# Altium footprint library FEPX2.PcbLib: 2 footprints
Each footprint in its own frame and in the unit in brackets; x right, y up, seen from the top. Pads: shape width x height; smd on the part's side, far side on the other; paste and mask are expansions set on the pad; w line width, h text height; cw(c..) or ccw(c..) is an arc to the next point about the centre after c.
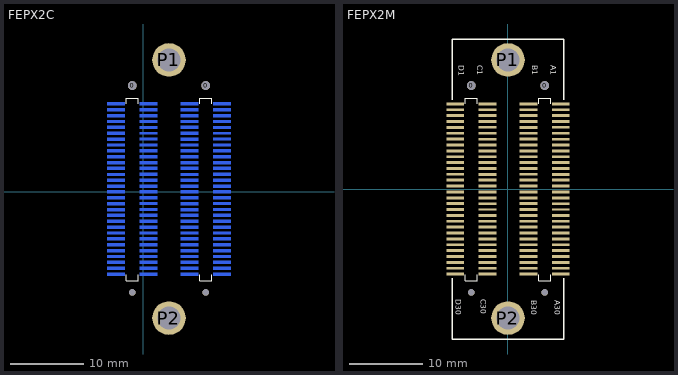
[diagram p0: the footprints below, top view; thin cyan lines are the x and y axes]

## FEPX2C [mm]
pads (126):
  round 0.889 hole 0.889: 0(-1.469,-13.691) 0(8.531,-13.691)
  round 1.2 hole 1.2: 0(-1.469,14.509) 0(8.531,14.509)
  rect 2.4x0.4 smd far side: A1(10.731,12.009) A2(10.731,11.209) A3(10.731,10.409) A4(10.731,9.609) A8(10.731,6.409) A9(10.731,5.609) A10(10.731,4.809) A11(10.731,4.009) A12(10.731,3.209) A13(10.731,2.409) A14(10.731,1.609) A15(10.731,0.809) A16(10.731,0.009) A17(10.731,-0.791) A20(10.731,-3.191) A21(10.731,-3.991) A22(10.731,-4.791) A23(10.731,-5.591) A24(10.731,-6.391) A25(10.731,-7.191) A26(10.731,-7.991) A27(10.731,-8.791) A28(10.731,-9.591) A29(10.731,-10.391) A30(10.731,-11.191) B1(6.331,12.009) B2(6.331,11.209) B3(6.331,10.409) B4(6.331,9.609) B5(6.331,8.809) B6(6.331,8.009) B7(6.331,7.209) B8(6.331,6.409) B9(6.331,5.609) B10(6.331,4.809) B11(6.331,4.009) B12(6.331,3.209) B14(6.331,1.609) B15(6.331,0.809) B16(6.331,0.009) B17(6.331,-0.791) B18(6.331,-1.591) B19(6.331,-2.391) B20(6.331,-3.191) B21(6.331,-3.991) B22(6.331,-4.791) B23(6.331,-5.591) B24(6.331,-6.391) B25(6.331,-7.191) B26(6.331,-7.991) B27(6.331,-8.791) B28(6.331,-9.591) B29(6.331,-10.391) B30(6.331,-11.191) C1(0.731,12.009) C2(0.731,11.209) C3(0.731,10.409) C4(0.731,9.609) C8(0.731,6.409) C9(0.731,5.609) C10(0.731,4.809) C11(0.731,4.009) C12(0.731,3.209) C13(0.731,2.409) C14(0.731,1.609) C15(0.731,0.809) C16(0.731,0.009) C17(0.731,-0.791) C20(0.731,-3.191) C21(0.731,-3.991) C22(0.731,-4.791) C23(0.731,-5.591) C24(0.731,-6.391) C25(0.731,-7.191) C26(0.731,-7.991) C27(0.731,-8.791) C28(0.731,-9.591) C29(0.731,-10.391) C30(0.731,-11.191) D1(-3.669,12.009) D2(-3.669,11.209) D3(-3.669,10.409) D4(-3.669,9.609) D5(-3.669,8.809) D6(-3.669,8.009) D7(-3.669,7.209) D8(-3.669,6.409) D9(-3.669,5.609) D10(-3.669,4.809) D11(-3.669,4.009) D12(-3.669,3.209) D14(-3.669,1.609) D15(-3.669,0.809) D16(-3.669,0.009) D17(-3.669,-0.791) D18(-3.669,-1.591) D19(-3.669,-2.391) D20(-3.669,-3.191) D21(-3.669,-3.991) D22(-3.669,-4.791) D23(-3.669,-5.591) D24(-3.669,-6.391) D25(-3.669,-7.191) D26(-3.669,-7.991) D27(-3.669,-8.791) D28(-3.669,-9.591) D29(-3.669,-10.391) D30(-3.669,-11.191)
  rect 2.4x0.33 smd far side: A5(10.731,8.809) A6(10.731,8.009) A7(10.731,7.209) A18(10.731,-1.591) A19(10.731,-2.391) B13(6.331,2.409) C5(0.731,8.809) C6(0.731,8.009) C7(0.731,7.209) C18(0.731,-1.591) C19(0.731,-2.391) D13(-3.669,2.409)
  round 4.57 hole 3.1: P1(3.531,18.009) P2(3.531,-17.191)
Top Overlay:
  lines w0.152: -2.269,-11.291 -2.269,-12.091 -0.669,-12.091 ; -2.269,12.009 -2.269,12.809 -0.669,12.809 -0.669,12.009 ; 7.731,12.009 7.731,12.809 9.331,12.809 9.331,12.009 ; 9.331,-11.291 9.331,-12.091 7.731,-12.091 ; -0.669,-12.091 -0.669,-11.291 -0.669,-12.091 ; 7.731,-12.091 7.731,-11.291 7.731,-12.091
Bottom Overlay:
  lines w0.203: -4.089,-11.786 -4.089,-20.041 11.151,-20.041 11.151,-11.786 ; -4.089,12.604 -4.089,20.859 11.151,20.859 11.151,12.604
  text "D1" at -3.2,17.247 h0.76
  text "C1" at -0.66,17.247 h0.76
  text "D30" at -3.581,-14.63 h0.76
  text "C30" at -0.152,-14.63 h0.76
  text "B30" at 6.706,-14.757 h0.76
  text "A30" at 9.881,-14.757 h0.76
  text "B1" at 6.833,17.247 h0.76
  text "A1" at 9.373,17.247 h0.76

## FEPX2M [mm]
pads (126):
  round 0.889 hole 0.889: 0(-5,-14.1) 0(5,-14.1)
  round 1.2 hole 1.2: 0(-5,14.1) 0(5,14.1)
  rect 2.4x0.4 smd: A1(7.2,11.6) A2(7.2,10.8) A3(7.2,10) A4(7.2,9.2) A8(7.2,6) A9(7.2,5.2) A10(7.2,4.4) A11(7.2,3.6) A12(7.2,2.8) A13(7.2,2) A14(7.2,1.2) A15(7.2,0.4) A16(7.2,-0.4) A17(7.2,-1.2) A20(7.2,-3.6) A21(7.2,-4.4) A22(7.2,-5.2) A23(7.2,-6) A24(7.2,-6.8) A25(7.2,-7.6) A26(7.2,-8.4) A27(7.2,-9.2) A28(7.2,-10) A29(7.2,-10.8) A30(7.2,-11.6) B1(2.8,11.6) B2(2.8,10.8) B3(2.8,10) B4(2.8,9.2) B5(2.8,8.4) B6(2.8,7.6) B7(2.8,6.8) B8(2.8,6) B9(2.8,5.2) B10(2.8,4.4) B11(2.8,3.6) B12(2.8,2.8) B14(2.8,1.2) B15(2.8,0.4) B16(2.8,-0.4) B17(2.8,-1.2) B18(2.8,-2) B19(2.8,-2.8) B20(2.8,-3.6) B21(2.8,-4.4) B22(2.8,-5.2) B23(2.8,-6) B24(2.8,-6.8) B25(2.8,-7.6) B26(2.8,-8.4) B27(2.8,-9.2) B28(2.8,-10) B29(2.8,-10.8) B30(2.8,-11.6) C1(-2.8,11.6) C2(-2.8,10.8) C3(-2.8,10) C4(-2.8,9.2) C8(-2.8,6) C9(-2.8,5.2) C10(-2.8,4.4) C11(-2.8,3.6) C12(-2.8,2.8) C13(-2.8,2) C14(-2.8,1.2) C15(-2.8,0.4) C16(-2.8,-0.4) C17(-2.8,-1.2) C20(-2.8,-3.6) C21(-2.8,-4.4) C22(-2.8,-5.2) C23(-2.8,-6) C24(-2.8,-6.8) C25(-2.8,-7.6) C26(-2.8,-8.4) C27(-2.8,-9.2) C28(-2.8,-10) C29(-2.8,-10.8) C30(-2.8,-11.6) D1(-7.2,11.6) D2(-7.2,10.8) D3(-7.2,10) D4(-7.2,9.2) D5(-7.2,8.4) D6(-7.2,7.6) D7(-7.2,6.8) D8(-7.2,6) D9(-7.2,5.2) D10(-7.2,4.4) D11(-7.2,3.6) D12(-7.2,2.8) D14(-7.2,1.2) D15(-7.2,0.4) D16(-7.2,-0.4) D17(-7.2,-1.2) D18(-7.2,-2) D19(-7.2,-2.8) D20(-7.2,-3.6) D21(-7.2,-4.4) D22(-7.2,-5.2) D23(-7.2,-6) D24(-7.2,-6.8) D25(-7.2,-7.6) D26(-7.2,-8.4) D27(-7.2,-9.2) D28(-7.2,-10) D29(-7.2,-10.8) D30(-7.2,-11.6)
  rect 2.4x0.33 smd: A5(7.2,8.4) A6(7.2,7.6) A7(7.2,6.8) A18(7.2,-2) A19(7.2,-2.8) B13(2.8,2) C5(-2.8,8.4) C6(-2.8,7.6) C7(-2.8,6.8) C18(-2.8,-2) C19(-2.8,-2.8) D13(-7.2,2)
  round 4.57 hole 3.1: P1(0,17.6) P2(0,-17.6)
Top Overlay:
  lines w0.152: -5.8,-11.7 -5.8,-12.5 -4.2,-12.5 ; -5.8,11.6 -5.8,12.4 -4.2,12.4 -4.2,11.6 ; 4.2,11.6 4.2,12.4 5.8,12.4 5.8,11.6 ; 5.8,-11.7 5.8,-12.5 4.2,-12.5 ; -4.2,-12.5 -4.2,-11.7 -4.2,-12.5 ; 4.2,-12.5 4.2,-11.7 4.2,-12.5
  lines w0.203: -7.62,-12.195 -7.62,-20.45 7.62,-20.45 7.62,-12.195 ; -7.62,12.195 -7.62,20.45 7.62,20.45 7.62,12.195
  text "B1" at 3.302,16.838 h0.76
  text "A1" at 5.842,16.838 h0.76
  text "B30" at 3.175,-15.166 h0.76
  text "A30" at 6.35,-15.166 h0.76
  text "D1" at -6.731,16.838 h0.76
  text "C1" at -4.191,16.838 h0.76
  text "D30" at -7.112,-15.039 h0.76
  text "C30" at -3.683,-15.039 h0.76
